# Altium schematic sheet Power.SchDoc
size 127 x 165 mm; SheetNumber: 1; SheetTotal: 1
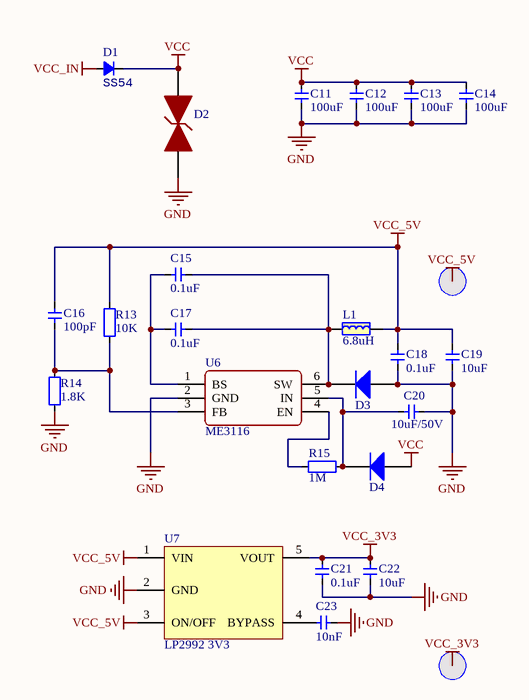
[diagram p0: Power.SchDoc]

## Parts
C11  100uF  [1206-CAP]
C12  100uF  [1206-CAP]
C13  100uF  [1206-CAP]
C14  100uF  [1206-CAP]
C15  0.1uF  [CAP_0402]
C16  100pF  [CAP_0402]
C17  0.1uF  [CAP_0402]
C18  0.1uF  [CAP_0402]
C19  10uF  [CAP_0402]
C20  10uF/50V  [CAP_0402]
C21  0.1uF  [CAP_0402]
C22  10uF  [CAP_0402]
C23  10nF  [CAP_0402]
D1  SS54  [DO-214AC]
D2  SMBJ28CA  [SMBJ-CA_MFG]  (value not drawn)
D3  二极管-5819W  [SOD-323]  (value not drawn)
D4  二极管-5819W  [SOD-323]  (value not drawn)
L1  6.8uH  [IND-201612]
R13  10K  [RES_0402]
R14  1.8K  [RES_0402]
R15  1M  [RES_0402]
T1  测试点  [TEST_PT]  (value not drawn)
T2  测试点  [TEST_PT]  (value not drawn)
U6  ME3116  [SOT23-6]
U7  LP2992 3V3  [SOT23-5]

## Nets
GND: C11.1 C12.1 C13.1 C14.1 C18.1 C19.1 C20.1 C21.1 C22.1 C23.1 D2.1 D3.1(A) R14.1 U6.2(GND) U7.2(GND)
VCC: C11.2 C12.2 C13.2 C14.2 D1.2(K) D2.2 D4.1(A)
VCC_3V3: C21.2 C22.2 T2.0 U7.5(VOUT)
VCC_5V: C16.1 C18.2 C19.2 L1.2 R13.2 T1.0 U7.1(VIN) U7.3(ON/OFF)
VCC_IN: D1.1(A)
NetC15_1: C15.1 C17.1 D3.2(K) L1.1 U6.6(SW)
NetC15_2: C15.2 C17.2 U6.1(BS)
NetC16_2: C16.2 R13.1 R14.2 U6.3(FB)
NetC20_2: C20.2 D4.2(K) R15.1 U6.5(IN)
NetC23_2: C23.2 U7.4(BYPASS)
NetR15_2: R15.2 U6.4(EN)

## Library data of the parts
C11-C14 = 电容-1206: Capacitor; Value: 0.1u
C15-C23 = 电容-0402: Capacitor; Value: 0.1u
D1 = Diode_SMA: Diode; Type: SMA
D3 D4 = 二极管-5819W: 40V
L1 = 电感-201612
R13-R15 = 电阻-0402: Resistor; Value: 22R
U6 = ME3116: DC-DC
U7 = LP2992: LDO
